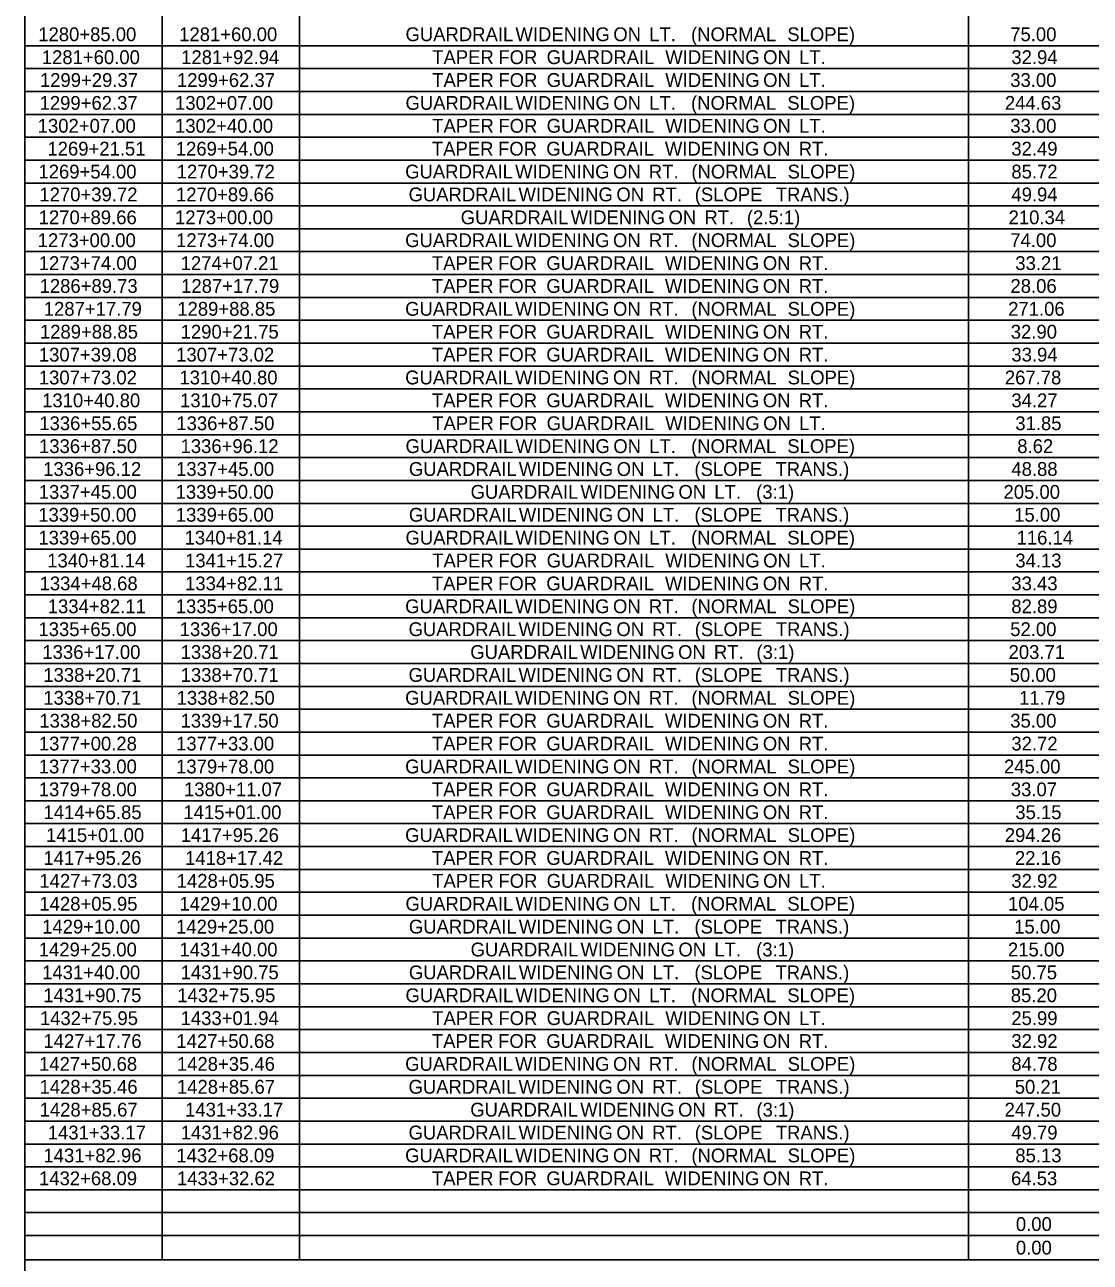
# Model space of a CAD drawing. Extents: x 1226590 to 1228573, y 151304 to 154224.
# Drawn here: x 1226590.3 to 1226976.1, y 153322.4 to 153770.6 of the extents above; entities that cross this region are included whole.
import ezdxf

# ---------------------------------------------------------------- set-up
doc = ezdxf.new("R2010")
doc.units = 0
doc.layers.add('R_Dimension', color=7, linetype='Continuous')

msp = doc.modelspace()

# ---------------------------------------------------------------- linework, layer by layer
at = {"layer": 'R_Dimension'}
for p, q in [((1226590.27, 152627.62), (1226590.27, 154214.43)), ((1226640, 153323.28), (1226640, 153928.75)), ((1226689.72, 153323.28), (1226689.72, 153928.75)), ((1226932.01, 153323.28), (1226932.01, 153928.75)), ((1226590.27, 153763), (1228572.93, 153763)), ((1226590.27, 153754.72), (1228572.93, 153754.72)), ((1226590.27, 153746.43), (1228572.93, 153746.43)), ((1226590.27, 153738.14), (1228572.93, 153738.14)), ((1226590.27, 153729.85), (1228572.93, 153729.85)), ((1226590.27, 153721.57), (1228572.93, 153721.57)), ((1226590.27, 153713.28), (1228572.93, 153713.28)), ((1226590.27, 153704.99), (1228572.93, 153704.99)), ((1226590.27, 153696.7), (1228572.93, 153696.7)), ((1226590.27, 153688.42), (1228572.93, 153688.42)), ((1226590.27, 153680.13), (1228572.93, 153680.13)), ((1226590.27, 153671.84), (1228572.93, 153671.84)), ((1226590.27, 153663.55), (1228572.93, 153663.55)), ((1226590.27, 153655.27), (1228572.93, 153655.27)), ((1226590.27, 153646.98), (1228572.93, 153646.98)), ((1226590.27, 153638.69), (1228572.93, 153638.69)), ((1226590.27, 153630.4), (1228572.93, 153630.4)), ((1226590.27, 153622.12), (1228572.93, 153622.12)), ((1226590.27, 153613.83), (1228572.93, 153613.83)), ((1226590.27, 153605.54), (1228572.93, 153605.54)), ((1226590.27, 153597.25), (1228572.93, 153597.25)), ((1226590.27, 153588.97), (1228572.93, 153588.97)), ((1226590.27, 153580.68), (1228572.93, 153580.68)), ((1226590.27, 153572.39), (1228572.93, 153572.39)), ((1226590.27, 153564.1), (1228572.93, 153564.1)), ((1226590.27, 153555.82), (1228572.93, 153555.82)), ((1226590.27, 153547.53), (1228572.93, 153547.53)), ((1226590.27, 153539.24), (1228572.93, 153539.24)), ((1226590.27, 153530.95), (1228572.93, 153530.95)), ((1226590.27, 153522.67), (1228572.93, 153522.67)), ((1226590.27, 153514.38), (1228572.93, 153514.38)), ((1226590.27, 153506.09), (1228572.93, 153506.09)), ((1226590.27, 153497.8), (1228572.93, 153497.8)), ((1226590.27, 153489.52), (1228572.93, 153489.52)), ((1226590.27, 153481.23), (1228572.93, 153481.23)), ((1226590.27, 153472.94), (1228572.93, 153472.94)), ((1226590.27, 153464.65), (1228572.93, 153464.65)), ((1226590.27, 153456.37), (1228572.93, 153456.37)), ((1226590.27, 153448.08), (1228572.93, 153448.08)), ((1226590.27, 153439.79), (1228572.93, 153439.79)), ((1226590.27, 153431.5), (1228572.93, 153431.5)), ((1226590.27, 153423.22), (1228572.93, 153423.22)), ((1226590.27, 153414.93), (1228572.93, 153414.93)), ((1226590.27, 153406.64), (1228572.93, 153406.64)), ((1226590.27, 153398.35), (1228572.93, 153398.35)), ((1226590.27, 153390.07), (1228572.93, 153390.07)), ((1226590.27, 153381.78), (1228572.93, 153381.78)), ((1226590.27, 153373.49), (1228572.93, 153373.49)), ((1226590.27, 153365.2), (1228572.93, 153365.2)), ((1226590.27, 153356.92), (1228572.93, 153356.92)), ((1226590.27, 153348.63), (1228572.93, 153348.63)), ((1226590.27, 153340.34), (1228572.93, 153340.34)), ((1226590.27, 153332.05), (1228572.93, 153332.05)), ((1226590.27, 153323.28), (1228572.93, 153323.28))]:
    msp.add_line(p, q, dxfattribs=at)

# ---------------------------------------------------------------- texts
for s, p in [(' (NORMAL', (1226829.66, 153764.65)), (' SLOPE)', (1226864.51, 153764.65)), ('1280+85.00', (1226595.15, 153764.65)), ('1281+60.00', (1226646.18, 153764.65)), ('GUARDRAIL', (1226728.13, 153764.65)), (' WIDENING', (1226766.08, 153764.65)), (' ON', (1226801.51, 153764.65)), (' LT.', (1226814.51, 153764.65)), ('75.00', (1226947.09, 153764.65)), ('1281+60.00', (1226596.45, 153756.36)), ('1281+92.94', (1226646.9, 153756.36)), ('TAPER', (1226737.81, 153756.36)), (' FOR', (1226759.9, 153756.36)), (' GUARDRAIL', (1226777.38, 153756.36)), (' WIDENING', (1226820.33, 153756.36)), (' ON', (1226855.77, 153756.36)), (' LT.', (1226868.76, 153756.36)), ('32.94', (1226947.5, 153756.36)), ('1299+29.37', (1226595.76, 153748.07)), ('1299+62.37', (1226645.37, 153748.07)), ('TAPER', (1226737.81, 153748.07)), (' FOR', (1226759.9, 153748.07)), (' GUARDRAIL', (1226777.38, 153748.07)), (' WIDENING', (1226820.33, 153748.07)), (' ON', (1226855.77, 153748.07)), (' LT.', (1226868.76, 153748.07)), ('33.00', (1226947.09, 153748.07)), ('1299+62.37', (1226595.64, 153739.79)), ('1302+07.00', (1226644.68, 153739.79)), ('GUARDRAIL', (1226728.13, 153739.79)), (' WIDENING', (1226766.08, 153739.79)), (' ON', (1226801.51, 153739.79)), (' LT.', (1226814.51, 153739.79)), (' (NORMAL', (1226829.66, 153739.79)), (' SLOPE)', (1226864.51, 153739.79)), ('244.63', (1226945.14, 153739.79)), ('1302+07.00', (1226594.96, 153731.5)), ('1302+40.00', (1226644.68, 153731.5)), ('TAPER', (1226737.81, 153731.5)), (' FOR', (1226759.9, 153731.5)), (' GUARDRAIL', (1226777.38, 153731.5)), (' WIDENING', (1226820.33, 153731.5)), (' ON', (1226855.77, 153731.5)), (' LT.', (1226868.76, 153731.5)), ('33.00', (1226947.09, 153731.5)), ('1269+21.51', (1226598.48, 153723.21)), ('1269+54.00', (1226644.96, 153723.21)), ('TAPER', (1226737.69, 153723.21)), (' FOR', (1226759.78, 153723.21)), (' GUARDRAIL', (1226777.26, 153723.21)), (' WIDENING', (1226820.21, 153723.21)), (' ON', (1226855.65, 153723.21)), (' RT.', (1226868.64, 153723.21)), ('32.49', (1226947.48, 153723.21)), ('1269+54.00', (1226595.23, 153714.92)), ('1270+39.72', (1226645.29, 153714.92)), ('GUARDRAIL', (1226728.01, 153714.92)), (' WIDENING', (1226765.96, 153714.92)), (' ON', (1226801.4, 153714.92)), (' RT.', (1226814.39, 153714.92)), (' (NORMAL', (1226829.78, 153714.92)), (' SLOPE)', (1226864.62, 153714.92)), ('85.72', (1226947.5, 153714.92)), ('1270+39.72', (1226595.57, 153706.64)), ('1270+89.66', (1226645.03, 153706.64)), ('GUARDRAIL', (1226729.23, 153706.64)), (' WIDENING', (1226767.18, 153706.64)), (' ON', (1226802.62, 153706.64)), (' RT.', (1226815.61, 153706.64)), (' (SLOPE', (1226831, 153706.64)), (' TRANS.)', (1226860.33, 153706.64)), ('49.94', (1226947.5, 153706.64)), ('1270+89.66', (1226595.31, 153698.35)), ('1273+00.00', (1226644.68, 153698.35)), ('GUARDRAIL', (1226748.11, 153698.35)), (' WIDENING', (1226786.06, 153698.35)), (' ON', (1226821.49, 153698.35)), (' RT.', (1226834.49, 153698.35)), (' (2.5:1)', (1226849.88, 153698.35)), ('210.34', (1226946.48, 153698.35)), ('1273+00.00', (1226594.96, 153690.06)), ('1273+74.00', (1226645.07, 153690.06)), ('GUARDRAIL', (1226728.01, 153690.06)), (' WIDENING', (1226765.96, 153690.06)), (' ON', (1226801.4, 153690.06)), (' RT.', (1226814.39, 153690.06)), (' (NORMAL', (1226829.78, 153690.06)), (' SLOPE)', (1226864.62, 153690.06)), ('74.00', (1226947.09, 153690.06)), ('1273+74.00', (1226595.35, 153681.77)), ('1274+07.21', (1226646.71, 153681.77)), ('TAPER', (1226737.69, 153681.77)), (' FOR', (1226759.78, 153681.77)), (' GUARDRAIL', (1226777.26, 153681.77)), (' WIDENING', (1226820.21, 153681.77)), (' ON', (1226855.65, 153681.77)), (' RT.', (1226868.64, 153681.77)), ('33.21', (1226948.92, 153681.77)), ('1286+89.73', (1226595.64, 153673.49)), ('1287+17.79', (1226646.89, 153673.49)), ('TAPER', (1226737.69, 153673.49)), (' FOR', (1226759.78, 153673.49)), (' GUARDRAIL', (1226777.26, 153673.49)), (' WIDENING', (1226820.21, 153673.49)), (' ON', (1226855.65, 153673.49)), (' RT.', (1226868.64, 153673.49)), ('28.06', (1226947.17, 153673.49)), ('1287+17.79', (1226597.16, 153665.2)), ('1289+88.85', (1226645.49, 153665.2)), ('GUARDRAIL', (1226728.01, 153665.2)), (' WIDENING', (1226765.96, 153665.2)), (' ON', (1226801.4, 153665.2)), (' RT.', (1226814.39, 153665.2)), (' (NORMAL', (1226829.78, 153665.2)), (' SLOPE)', (1226864.62, 153665.2)), ('271.06', (1226946.34, 153665.2)), ('1289+88.85', (1226595.76, 153656.91)), ('1290+21.75', (1226646.71, 153656.91)), ('TAPER', (1226737.69, 153656.91)), (' FOR', (1226759.78, 153656.91)), (' GUARDRAIL', (1226777.26, 153656.91)), (' WIDENING', (1226820.21, 153656.91)), (' ON', (1226855.65, 153656.91)), (' RT.', (1226868.64, 153656.91)), ('32.90', (1226947.28, 153656.91)), ('1307+39.08', (1226595.37, 153648.62)), ('1307+73.02', (1226645.09, 153648.62)), ('TAPER', (1226737.69, 153648.62)), (' FOR', (1226759.78, 153648.62)), (' GUARDRAIL', (1226777.26, 153648.62)), (' WIDENING', (1226820.21, 153648.62)), (' ON', (1226855.65, 153648.62)), (' RT.', (1226868.64, 153648.62)), ('33.94', (1226947.5, 153648.62)), ('1307+73.02', (1226595.37, 153640.34)), ('1310+40.80', (1226646.29, 153640.34)), ('GUARDRAIL', (1226728.01, 153640.34)), (' WIDENING', (1226765.96, 153640.34)), (' ON', (1226801.4, 153640.34)), (' RT.', (1226814.39, 153640.34)), (' (NORMAL', (1226829.78, 153640.34)), (' SLOPE)', (1226864.62, 153640.34)), ('267.78', (1226945.14, 153640.34)), ('1310+40.80', (1226596.57, 153632.05)), ('1310+75.07', (1226646.51, 153632.05)), ('TAPER', (1226737.69, 153632.05)), (' FOR', (1226759.78, 153632.05)), (' GUARDRAIL', (1226777.26, 153632.05)), (' WIDENING', (1226820.21, 153632.05)), (' ON', (1226855.65, 153632.05)), (' RT.', (1226868.64, 153632.05)), ('34.27', (1226947.5, 153632.05)), ('1336+55.65', (1226595.53, 153623.76)), ('1336+87.50', (1226645.15, 153623.76)), ('TAPER', (1226737.81, 153623.76)), (' FOR', (1226759.9, 153623.76)), (' GUARDRAIL', (1226777.38, 153623.76)), (' WIDENING', (1226820.33, 153623.76)), (' ON', (1226855.77, 153623.76)), (' LT.', (1226868.76, 153623.76)), ('31.85', (1226948.92, 153623.76)), ('1336+87.50', (1226595.43, 153615.47)), ('1336+96.12', (1226646.67, 153615.47)), ('GUARDRAIL', (1226728.13, 153615.47)), (' WIDENING', (1226766.08, 153615.47)), (' ON', (1226801.51, 153615.47)), (' LT.', (1226814.51, 153615.47)), (' (NORMAL', (1226829.66, 153615.47)), (' SLOPE)', (1226864.51, 153615.47)), ('8.62', (1226949.63, 153615.47)), ('1336+96.12', (1226596.94, 153607.19)), ('1337+45.00', (1226645.07, 153607.19)), ('GUARDRAIL', (1226729.35, 153607.19)), (' WIDENING', (1226767.3, 153607.19)), (' ON', (1226802.73, 153607.19)), (' LT.', (1226815.73, 153607.19)), (' (SLOPE', (1226830.88, 153607.19)), (' TRANS.)', (1226860.21, 153607.19)), ('48.88', (1226947.5, 153607.19)), (' (3:1)', (1226853.23, 153598.9)), ('1337+45.00', (1226595.35, 153598.9)), ('1339+50.00', (1226644.88, 153598.9)), ('GUARDRAIL', (1226751.69, 153598.9)), (' WIDENING', (1226789.64, 153598.9)), (' ON', (1226825.08, 153598.9)), (' LT.', (1226838.07, 153598.9)), ('205.00', (1226944.65, 153598.9)), ('1339+50.00', (1226595.15, 153590.61)), ('1339+65.00', (1226644.96, 153590.61)), ('GUARDRAIL', (1226729.35, 153590.61)), (' WIDENING', (1226767.3, 153590.61)), (' ON', (1226802.73, 153590.61)), (' LT.', (1226815.73, 153590.61)), (' (SLOPE', (1226830.88, 153590.61)), (' TRANS.)', (1226860.21, 153590.61)), ('15.00', (1226948.5, 153590.61)), ('1339+65.00', (1226595.23, 153582.32)), ('1340+81.14', (1226648.13, 153582.32)), ('GUARDRAIL', (1226728.13, 153582.32)), (' WIDENING', (1226766.08, 153582.32)), (' ON', (1226801.51, 153582.32)), (' LT.', (1226814.51, 153582.32)), (' (NORMAL', (1226829.66, 153582.32)), (' SLOPE)', (1226864.51, 153582.32)), ('116.14', (1226949.39, 153582.32)), ('1340+81.14', (1226598.4, 153574.04)), ('1341+15.27', (1226648.32, 153574.04)), ('TAPER', (1226737.81, 153574.04)), (' FOR', (1226759.9, 153574.04)), (' GUARDRAIL', (1226777.38, 153574.04)), (' WIDENING', (1226820.33, 153574.04)), (' ON', (1226855.77, 153574.04)), (' LT.', (1226868.76, 153574.04)), ('34.13', (1226948.92, 153574.04)), ('1334+48.68', (1226595.64, 153565.75)), ('1334+82.11', (1226648.32, 153565.75)), ('TAPER', (1226737.69, 153565.75)), (' FOR', (1226759.78, 153565.75)), (' GUARDRAIL', (1226777.26, 153565.75)), (' WIDENING', (1226820.21, 153565.75)), (' ON', (1226855.65, 153565.75)), (' RT.', (1226868.64, 153565.75)), ('33.43', (1226947.5, 153565.75)), ('1334+82.11', (1226598.6, 153557.46)), ('1335+65.00', (1226644.96, 153557.46)), ('GUARDRAIL', (1226728.01, 153557.46)), (' WIDENING', (1226765.96, 153557.46)), (' ON', (1226801.4, 153557.46)), (' RT.', (1226814.39, 153557.46)), (' (NORMAL', (1226829.78, 153557.46)), (' SLOPE)', (1226864.62, 153557.46)), ('82.89', (1226947.48, 153557.46)), ('1335+65.00', (1226595.23, 153549.17)), ('1336+17.00', (1226646.37, 153549.17)), ('GUARDRAIL', (1226729.23, 153549.17)), (' WIDENING', (1226767.18, 153549.17)), (' ON', (1226802.62, 153549.17)), (' RT.', (1226815.61, 153549.17)), (' (SLOPE', (1226831, 153549.17)), (' TRANS.)', (1226860.33, 153549.17)), ('52.00', (1226947.09, 153549.17)), ('1336+17.00', (1226596.65, 153540.89)), ('1338+20.71', (1226646.71, 153540.89)), ('GUARDRAIL', (1226751.57, 153540.89)), (' WIDENING', (1226789.53, 153540.89)), (' ON', (1226824.96, 153540.89)), (' RT.', (1226837.95, 153540.89)), (' (3:1)', (1226853.34, 153540.89)), ('203.71', (1226946.48, 153540.89)), ('1338+20.71', (1226596.98, 153532.6)), ('1338+70.71', (1226646.71, 153532.6)), ('GUARDRAIL', (1226729.23, 153532.6)), (' WIDENING', (1226767.18, 153532.6)), (' ON', (1226802.62, 153532.6)), (' RT.', (1226815.61, 153532.6)), (' (SLOPE', (1226831, 153532.6)), (' TRANS.)', (1226860.33, 153532.6)), ('50.00', (1226946.89, 153532.6)), ('1338+70.71', (1226596.98, 153524.31)), ('1338+82.50', (1226645.27, 153524.31)), ('GUARDRAIL', (1226728.01, 153524.31)), (' WIDENING', (1226765.96, 153524.31)), (' ON', (1226801.4, 153524.31)), (' RT.', (1226814.39, 153524.31)), (' (NORMAL', (1226829.78, 153524.31)), (' SLOPE)', (1226864.62, 153524.31)), ('11.79', (1226950.32, 153524.31)), ('1338+82.50', (1226595.55, 153516.02)), ('1339+17.50', (1226646.69, 153516.02)), ('TAPER', (1226737.69, 153516.02)), (' FOR', (1226759.78, 153516.02)), (' GUARDRAIL', (1226777.26, 153516.02)), (' WIDENING', (1226820.21, 153516.02)), (' ON', (1226855.65, 153516.02)), (' RT.', (1226868.64, 153516.02)), ('35.00', (1226947.09, 153516.02)), ('1377+00.28', (1226595.37, 153507.74)), ('1377+33.00', (1226645.07, 153507.74)), ('TAPER', (1226737.69, 153507.74)), (' FOR', (1226759.78, 153507.74)), (' GUARDRAIL', (1226777.26, 153507.74)), (' WIDENING', (1226820.21, 153507.74)), (' ON', (1226855.65, 153507.74)), (' RT.', (1226868.64, 153507.74)), ('32.72', (1226947.5, 153507.74)), ('1377+33.00', (1226595.35, 153499.45)), ('1379+78.00', (1226645.07, 153499.45)), ('GUARDRAIL', (1226728.01, 153499.45)), (' WIDENING', (1226765.96, 153499.45)), (' ON', (1226801.4, 153499.45)), (' RT.', (1226814.39, 153499.45)), (' (NORMAL', (1226829.78, 153499.45)), (' SLOPE)', (1226864.62, 153499.45)), ('245.00', (1226944.84, 153499.45)), ('1379+78.00', (1226595.35, 153491.16)), ('1380+11.07', (1226647.93, 153491.16)), ('TAPER', (1226737.69, 153491.16)), (' FOR', (1226759.78, 153491.16)), (' GUARDRAIL', (1226777.26, 153491.16)), (' WIDENING', (1226820.21, 153491.16)), (' ON', (1226855.65, 153491.16)), (' RT.', (1226868.64, 153491.16)), ('33.07', (1226947.3, 153491.16)), ('1414+65.85', (1226597.06, 153482.87)), ('1415+01.00', (1226647.71, 153482.87)), ('TAPER', (1226737.69, 153482.87)), (' FOR', (1226759.78, 153482.87)), (' GUARDRAIL', (1226777.26, 153482.87)), (' WIDENING', (1226820.21, 153482.87)), (' ON', (1226855.65, 153482.87)), (' RT.', (1226868.64, 153482.87)), ('35.15', (1226948.92, 153482.87)), ('1415+01.00', (1226597.99, 153474.59)), ('1417+95.26', (1226646.77, 153474.59)), ('GUARDRAIL', (1226728.01, 153474.59)), (' WIDENING', (1226765.96, 153474.59)), (' ON', (1226801.4, 153474.59)), (' RT.', (1226814.39, 153474.59)), (' (NORMAL', (1226829.78, 153474.59)), (' SLOPE)', (1226864.62, 153474.59)), ('294.26', (1226945.12, 153474.59)), ('1417+95.26', (1226597.04, 153466.3)), ('1418+17.42', (1226648.32, 153466.3)), ('TAPER', (1226737.69, 153466.3)), (' FOR', (1226759.78, 153466.3)), (' GUARDRAIL', (1226777.26, 153466.3)), (' WIDENING', (1226820.21, 153466.3)), (' ON', (1226855.65, 153466.3)), (' RT.', (1226868.64, 153466.3)), ('22.16', (1226948.78, 153466.3)), ('1427+73.03', (1226595.57, 153458.01)), ('1428+05.95', (1226645.29, 153458.01)), ('TAPER', (1226737.81, 153458.01)), (' FOR', (1226759.9, 153458.01)), (' GUARDRAIL', (1226777.38, 153458.01)), (' WIDENING', (1226820.33, 153458.01)), (' ON', (1226855.77, 153458.01)), (' LT.', (1226868.76, 153458.01)), ('32.92', (1226947.5, 153458.01)), ('1428+05.95', (1226595.57, 153449.72)), ('1429+10.00', (1226646.29, 153449.72)), ('GUARDRAIL', (1226728.13, 153449.72)), (' WIDENING', (1226766.08, 153449.72)), (' ON', (1226801.51, 153449.72)), (' LT.', (1226814.51, 153449.72)), (' (NORMAL', (1226829.66, 153449.72)), (' SLOPE)', (1226864.51, 153449.72)), ('104.05', (1226946.28, 153449.72)), ('1429+10.00', (1226596.57, 153441.44)), ('1429+25.00', (1226645.07, 153441.44)), ('GUARDRAIL', (1226729.35, 153441.44)), (' WIDENING', (1226767.3, 153441.44)), (' ON', (1226802.73, 153441.44)), (' LT.', (1226815.73, 153441.44)), (' (SLOPE', (1226830.88, 153441.44)), (' TRANS.)', (1226860.21, 153441.44)), ('15.00', (1226948.5, 153441.44)), ('1429+25.00', (1226595.35, 153433.15)), ('1431+40.00', (1226646.29, 153433.15)), ('GUARDRAIL', (1226751.69, 153433.15)), (' WIDENING', (1226789.64, 153433.15)), (' ON', (1226825.08, 153433.15)), (' (3:1)', (1226853.23, 153433.15)), ('215.00', (1226946.26, 153433.15)), (' LT.', (1226838.07, 153433.15)), ('1431+40.00', (1226596.57, 153424.86)), ('1431+90.75', (1226646.71, 153424.86)), ('GUARDRAIL', (1226729.35, 153424.86)), (' WIDENING', (1226767.3, 153424.86)), (' ON', (1226802.73, 153424.86)), (' LT.', (1226815.73, 153424.86)), (' (SLOPE', (1226830.88, 153424.86)), (' TRANS.)', (1226860.21, 153424.86)), ('50.75', (1226947.3, 153424.86)), ('1431+90.75', (1226596.98, 153416.57)), ('1432+75.95', (1226645.49, 153416.57)), ('GUARDRAIL', (1226728.13, 153416.57)), (' WIDENING', (1226766.08, 153416.57)), (' ON', (1226801.51, 153416.57)), (' LT.', (1226814.51, 153416.57)), (' (NORMAL', (1226829.66, 153416.57)), (' SLOPE)', (1226864.51, 153416.57)), ('85.20', (1226947.28, 153416.57)), ('1432+75.95', (1226595.76, 153408.29)), ('1433+01.94', (1226646.71, 153408.29)), ('TAPER', (1226737.81, 153408.29)), (' FOR', (1226759.9, 153408.29)), (' GUARDRAIL', (1226777.38, 153408.29)), (' WIDENING', (1226820.33, 153408.29)), (' ON', (1226855.77, 153408.29)), (' LT.', (1226868.76, 153408.29)), ('25.99', (1226947.48, 153408.29)), ('1427+17.76', (1226597.04, 153400)), ('1427+50.68', (1226645.17, 153400)), ('TAPER', (1226737.69, 153400)), (' FOR', (1226759.78, 153400)), (' GUARDRAIL', (1226777.26, 153400)), (' WIDENING', (1226820.21, 153400)), (' ON', (1226855.65, 153400)), (' RT.', (1226868.64, 153400)), ('32.92', (1226947.5, 153400)), ('1427+50.68', (1226595.45, 153391.71)), ('1428+35.46', (1226645.35, 153391.71)), ('GUARDRAIL', (1226728.01, 153391.71)), (' WIDENING', (1226765.96, 153391.71)), (' ON', (1226801.4, 153391.71)), (' RT.', (1226814.39, 153391.71)), (' (NORMAL', (1226829.78, 153391.71)), (' SLOPE)', (1226864.62, 153391.71)), ('84.78', (1226947.5, 153391.71)), ('1428+35.46', (1226595.62, 153383.42)), ('1428+85.67', (1226645.37, 153383.42)), ('GUARDRAIL', (1226729.23, 153383.42)), (' WIDENING', (1226767.18, 153383.42)), (' ON', (1226802.62, 153383.42)), (' RT.', (1226815.61, 153383.42)), (' (SLOPE', (1226831, 153383.42)), (' TRANS.)', (1226860.33, 153383.42)), ('50.21', (1226948.72, 153383.42)), ('1428+85.67', (1226595.64, 153375.14)), ('1431+33.17', (1226648.32, 153375.14)), ('GUARDRAIL', (1226751.57, 153375.14)), (' WIDENING', (1226789.53, 153375.14)), (' ON', (1226824.96, 153375.14)), (' RT.', (1226837.95, 153375.14)), (' (3:1)', (1226853.34, 153375.14)), ('247.50', (1226945.04, 153375.14)), ('1431+33.17', (1226598.6, 153366.85)), ('1431+82.96', (1226646.77, 153366.85)), ('GUARDRAIL', (1226729.23, 153366.85)), (' WIDENING', (1226767.18, 153366.85)), (' ON', (1226802.62, 153366.85)), (' RT.', (1226815.61, 153366.85)), (' (SLOPE', (1226831, 153366.85)), (' TRANS.)', (1226860.33, 153366.85)), ('49.79', (1226947.48, 153366.85)), ('1431+82.96', (1226597.04, 153358.56)), ('1432+68.09', (1226645.15, 153358.56)), ('GUARDRAIL', (1226728.01, 153358.56)), (' WIDENING', (1226765.96, 153358.56)), (' ON', (1226801.4, 153358.56)), (' RT.', (1226814.39, 153358.56)), (' (NORMAL', (1226829.78, 153358.56)), (' SLOPE)', (1226864.62, 153358.56)), ('85.13', (1226948.92, 153358.56)), ('1432+68.09', (1226595.43, 153350.27)), ('1433+32.62', (1226645.37, 153350.27)), ('TAPER', (1226737.69, 153350.27)), (' FOR', (1226759.78, 153350.27)), (' GUARDRAIL', (1226777.26, 153350.27)), (' WIDENING', (1226820.21, 153350.27)), (' ON', (1226855.65, 153350.27)), (' RT.', (1226868.64, 153350.27)), ('64.53', (1226947.38, 153350.27)), ('0.00', (1226949.13, 153333.7)), ('0.00', (1226949.13, 153325.17))]:
    msp.add_text(s, height=5, dxfattribs=at).set_placement(p)

doc.saveas('drawing.dxf')
